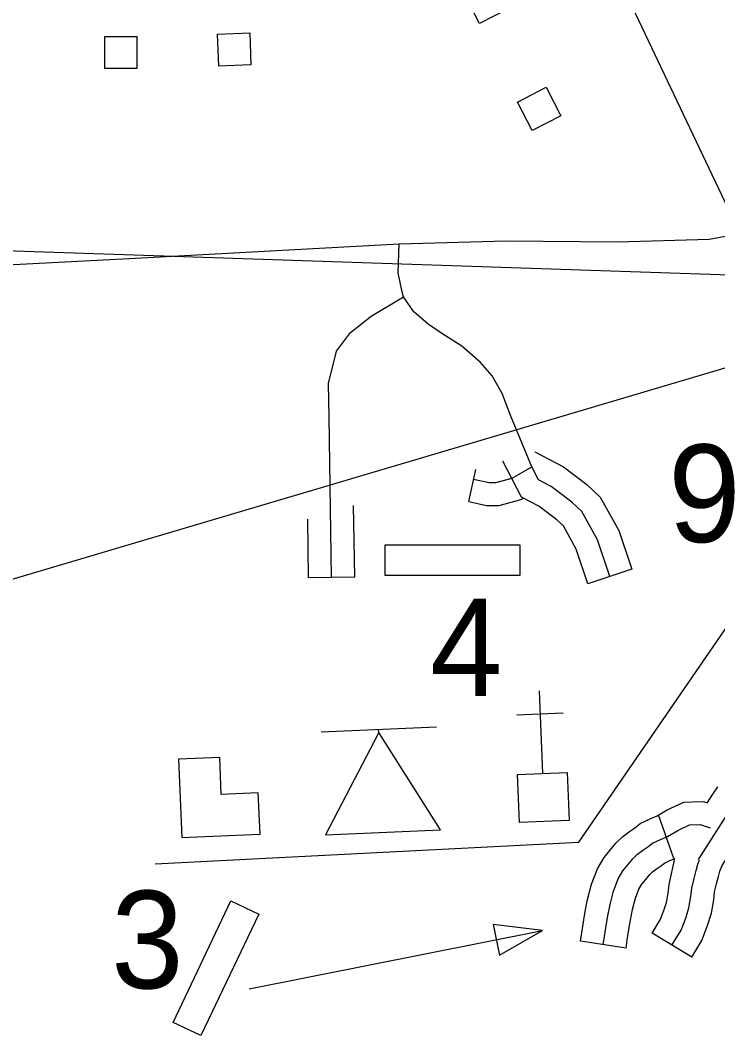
# Model space of a CAD drawing. Extents: x 1671357 to 13005564, y 567358 to 14261451.
# Drawn here: x 12758298.676 to 12758299.433, y 14259943.158 to 14259944.26 of the extents above; entities that cross this region are included whole.
import ezdxf

# ---------------------------------------------------------------- set-up
doc = ezdxf.new("R2010")
doc.units = 0
for name, color, linetype in [('15', 7, 'Continuous'), ('31', 7, 'Continuous'), ('32', 7, 'Continuous'), ('56', 7, 'Continuous'), ('57', 7, 'Continuous'), ('58', 7, 'Continuous'), ('Default', 7, 'Continuous')]:
    doc.layers.add(name, color=color, linetype=linetype)

msp = doc.modelspace()

# ---------------------------------------------------------------- linework, layer by layer
at = {"layer": '15'}
msp.add_lwpolyline([(12758299.4787, 14259943.9824), (12758298.9769, 14259945.0388), (12758298.8418, 14259945.317), (12758298.5465, 14259945.943), (12758298.5141, 14259946.0019), (12758298.4993, 14259946.0256), (12758298.4548, 14259946.0826), (12758298.3783, 14259946.1775), (12758298.3689, 14259946.1917), (12758298.3456, 14259946.2211), (12758298.3125, 14259946.2727), (12758298.2918, 14259946.313), (12758298.1478, 14259946.6216)], dxfattribs=at)
at = {"layer": '31'}
for p, q in [((12758299.1626, 14259943.7376), (12758299.1701, 14259943.7726)), ((12758299.3394, 14259943.6644), (12758299.2919, 14259943.6484)), ((12758299.0388, 14259943.6557), (12758298.9888, 14259943.6549))]:
    msp.add_line(p, q, dxfattribs=at)
for points in [[(12758299.3156, 14259943.6564), (12758299.3023, 14259943.6961), (12758299.2852, 14259943.7269), (12758299.2745, 14259943.7371), (12758299.252, 14259943.7539), (12758299.2384, 14259943.7611), (12758299.2311, 14259943.7752), (12758299.2084, 14259943.8302), (12758299.199, 14259943.8549), (12758299.1881, 14259943.8742), (12758299.1755, 14259943.8884), (12758299.155, 14259943.9063), (12758299.1334, 14259943.9198), (12758299.1186, 14259943.9299), (12758299.103, 14259943.9433), (12758299.0917, 14259943.9596), (12758299.09, 14259943.9665), (12758299.0859, 14259943.9858), (12758299.0869, 14259944.0173)], [(12758299.0138, 14259943.6553), (12758299.0111, 14259943.8291), (12758299.0105, 14259943.8656), (12758299.019, 14259943.9008), (12758299.0342, 14259943.9209), (12758299.0568, 14259943.9386), (12758299.0917, 14259943.9596)], [(12758299.2341, 14259943.7915), (12758299.2654, 14259943.7752), (12758299.2906, 14259943.7563), (12758299.3053, 14259943.7423), (12758299.3253, 14259943.7062), (12758299.3394, 14259943.6644)], [(12758299.2919, 14259943.6484), (12758299.2792, 14259943.6859), (12758299.2652, 14259943.7114), (12758299.2583, 14259943.718), (12758299.2386, 14259943.7327), (12758299.2198, 14259943.7425), (12758299.1997, 14259943.7813)], [(12758299.1679, 14259943.7621), (12758299.1847, 14259943.7584), (12758299.1921, 14259943.7584), (12758299.2096, 14259943.7632), (12758299.2311, 14259943.7752)], [(12758299.1626, 14259943.7376), (12758299.182, 14259943.7334), (12758299.1954, 14259943.7334), (12758299.2191, 14259943.7398), (12758299.2219, 14259943.7414)], [(12758299.0388, 14259943.6557), (12758299.0376, 14259943.7333)], [(12758298.9888, 14259943.6549), (12758298.9878, 14259943.7185)]]:
    msp.add_lwpolyline(points, dxfattribs=at)
at = {"layer": '32'}
for p, q in [((12758299.385, 14259943.3505), (12758299.3685, 14259943.3978)), ((12758299.4045, 14259943.2437), (12758299.3617, 14259943.2697)), ((12758299.3332, 14259943.2533), (12758299.2837, 14259943.261))]:
    msp.add_line(p, q, dxfattribs=at)
for points in [[(12758296.5582, 14259948.9778), (12758296.5804, 14259948.3887), (12758296.6031, 14259947.4486), (12758296.6261, 14259946.6026), (12758296.6856, 14259943.8968), (12758296.6973, 14259943.8869), (12758296.7248, 14259943.8847), (12758297.3044, 14259943.9433), (12758297.3789, 14259943.9431), (12758297.6003, 14259943.9509), (12758298.3787, 14259943.9834), (12758298.5205, 14259943.9868), (12758298.6547, 14259943.9942), (12758298.801, 14259944.0018), (12758299.0869, 14259944.0173), (12758299.203, 14259944.0203), (12758299.3239, 14259944.0194), (12758299.4233, 14259944.0223), (12758299.5412, 14259944.0441)], [(12758299.4119, 14259943.3495), (12758299.4485, 14259943.4067), (12758299.4579, 14259943.4209), (12758299.4728, 14259943.4329), (12758299.4825, 14259943.4393), (12758299.4991, 14259943.4484), (12758299.5126, 14259943.4621), (12758299.5259, 14259943.4781), (12758299.5369, 14259943.4949), (12758299.5521, 14259943.515), (12758299.5668, 14259943.5294), (12758299.6053, 14259943.5585)], [(12758299.4216, 14259943.4112), (12758299.4275, 14259943.4204), (12758299.4327, 14259943.4282)], [(12758299.2837, 14259943.261), (12758299.2851, 14259943.2698), (12758299.2873, 14259943.2842), (12758299.2889, 14259943.2929), (12758299.2915, 14259943.3062), (12758299.2958, 14259943.3226), (12758299.3021, 14259943.3395), (12758299.3094, 14259943.3515), (12758299.3157, 14259943.3592), (12758299.3222, 14259943.3673), (12758299.3296, 14259943.3743), (12758299.3369, 14259943.3798), (12758299.3423, 14259943.3836), (12758299.3487, 14259943.3884), (12758299.3601, 14259943.394), (12758299.3671, 14259943.397), (12758299.378, 14259943.4033), (12758299.3961, 14259943.4118), (12758299.4051, 14259943.4121)], [(12758299.4051, 14259943.4121), (12758299.4174, 14259943.4125), (12758299.4216, 14259943.4111)], [(12758299.4045, 14259943.2437), (12758299.4154, 14259943.2616), (12758299.4218, 14259943.2779), (12758299.4258, 14259943.2913), (12758299.4284, 14259943.3056), (12758299.4294, 14259943.3143), (12758299.4313, 14259943.3229), (12758299.4335, 14259943.3312), (12758299.435, 14259943.3367), (12758299.4374, 14259943.3429), (12758299.4695, 14259943.393), (12758299.4744, 14259943.4004)], [(12758299.3084, 14259943.2571), (12758299.3098, 14259943.2659), (12758299.312, 14259943.28), (12758299.3135, 14259943.2883), (12758299.316, 14259943.3006), (12758299.3197, 14259943.3151), (12758299.3247, 14259943.3285), (12758299.3299, 14259943.337), (12758299.3351, 14259943.3435), (12758299.3406, 14259943.3503), (12758299.3458, 14259943.3552), (12758299.3515, 14259943.3595), (12758299.357, 14259943.3633), (12758299.3618, 14259943.367), (12758299.3705, 14259943.3712), (12758299.3783, 14259943.3745), (12758299.3896, 14259943.381), (12758299.4021, 14259943.3869), (12758299.4138, 14259943.3873), (12758299.4244, 14259943.3838)], [(12758299.3332, 14259943.2533), (12758299.3345, 14259943.262), (12758299.3367, 14259943.2758), (12758299.3381, 14259943.2836), (12758299.3404, 14259943.2951), (12758299.3436, 14259943.3076), (12758299.3473, 14259943.3174), (12758299.3504, 14259943.3226), (12758299.3546, 14259943.3277), (12758299.3591, 14259943.3332), (12758299.362, 14259943.336), (12758299.3662, 14259943.3392), (12758299.3718, 14259943.3431), (12758299.375, 14259943.3455), (12758299.3809, 14259943.3484), (12758299.3853, 14259943.3503)], [(12758299.3617, 14259943.2697), (12758299.3704, 14259943.2839), (12758299.3744, 14259943.2941), (12758299.377, 14259943.303), (12758299.3789, 14259943.313), (12758299.3799, 14259943.3225), (12758299.3861, 14259943.3507)], [(12758299.3831, 14259943.2567), (12758299.3929, 14259943.2728), (12758299.3981, 14259943.286), (12758299.4014, 14259943.2972), (12758299.4036, 14259943.3093), (12758299.4047, 14259943.3184), (12758299.407, 14259943.3289), (12758299.4093, 14259943.3377), (12758299.4111, 14259943.3444), (12758299.4129, 14259943.3492)]]:
    msp.add_lwpolyline(points, dxfattribs=at)
at = {"layer": '56'}
for points in [[(12758299.2053, 14259944.2719), (12758299.1744, 14259944.2562), (12758299.1585, 14259944.2872), (12758299.1895, 14259944.303)], [(12758298.7676, 14259944.2074), (12758298.7676, 14259944.2421), (12758298.8025, 14259944.2421), (12758298.8025, 14259944.2074)], [(12758298.8915, 14259944.2099), (12758298.89, 14259944.2446), (12758298.9249, 14259944.2461), (12758298.9263, 14259944.2114)], [(12758299.2155, 14259944.171), (12758299.2464, 14259944.187), (12758299.2624, 14259944.156), (12758299.2315, 14259944.1401)], [(12758299.072, 14259943.6573), (12758299.072, 14259943.6907), (12758299.2181, 14259943.6907), (12758299.2181, 14259943.6573)], [(12758298.9045, 14259943.3046), (12758298.9347, 14259943.2903), (12758298.8719, 14259943.1584), (12758298.8417, 14259943.1727)], [(12758299.1892, 14259943.279), (12758299.1959, 14259943.2456), (12758299.2427, 14259943.2723)]]:
    msp.add_lwpolyline(points, close=True, dxfattribs=at)
for points in [[(12758298.8222, 14259943.3448), (12758299.282, 14259943.3681), (12758299.5629, 14259943.7768)], [(12758298.9242, 14259943.2091), (12758299.2427, 14259943.2723)]]:
    msp.add_lwpolyline(points, dxfattribs=at)
at = {"layer": '57'}
for p, q in [((12758299.2388, 14259943.5325), (12758299.2426, 14259943.4427)), ((12758299.2148, 14259943.5064), (12758299.2649, 14259943.5086)), ((12758299.0023, 14259943.4879), (12758299.1274, 14259943.4933)), ((12758299.065, 14259943.4873), (12758299.007, 14259943.3763)), ((12758299.065, 14259943.4873), (12758299.0648, 14259943.4906)), ((12758299.1321, 14259943.3816), (12758299.065, 14259943.4873)), ((12758299.007, 14259943.3763), (12758299.1321, 14259943.3816))]:
    msp.add_line(p, q, dxfattribs=at)
msp.add_lwpolyline([(12758299.2178, 14259943.3895), (12758299.2155, 14259943.4416), (12758299.2695, 14259943.4439), (12758299.2717, 14259943.3918)], close=True, dxfattribs=at)
at = {"layer": '58'}
msp.add_lwpolyline([(12758298.8514, 14259943.3735), (12758298.9361, 14259943.3771), (12758298.9342, 14259943.4218), (12758298.8941, 14259943.4201), (12758298.8924, 14259943.4601), (12758298.8478, 14259943.4582)], close=True, dxfattribs=at)
at = {"layer": 'Default'}
msp.add_lwpolyline([(12758294.0003, 14259944.1661), (12758299.7478, 14259943.9734), (12758297.4988, 14259943.307), (12758298.2165, 14259944.0247)], dxfattribs=at)

# ---------------------------------------------------------------- texts
at = {"layer": '56'}
for s, p in [('9', (12758299.379, 14259943.6937)), ('4', (12758299.1205, 14259943.5267)), ('3', (12758298.7745, 14259943.2097))]:
    msp.add_text(s, height=0.1058, dxfattribs=at).set_placement(p)

doc.saveas('drawing.dxf')
